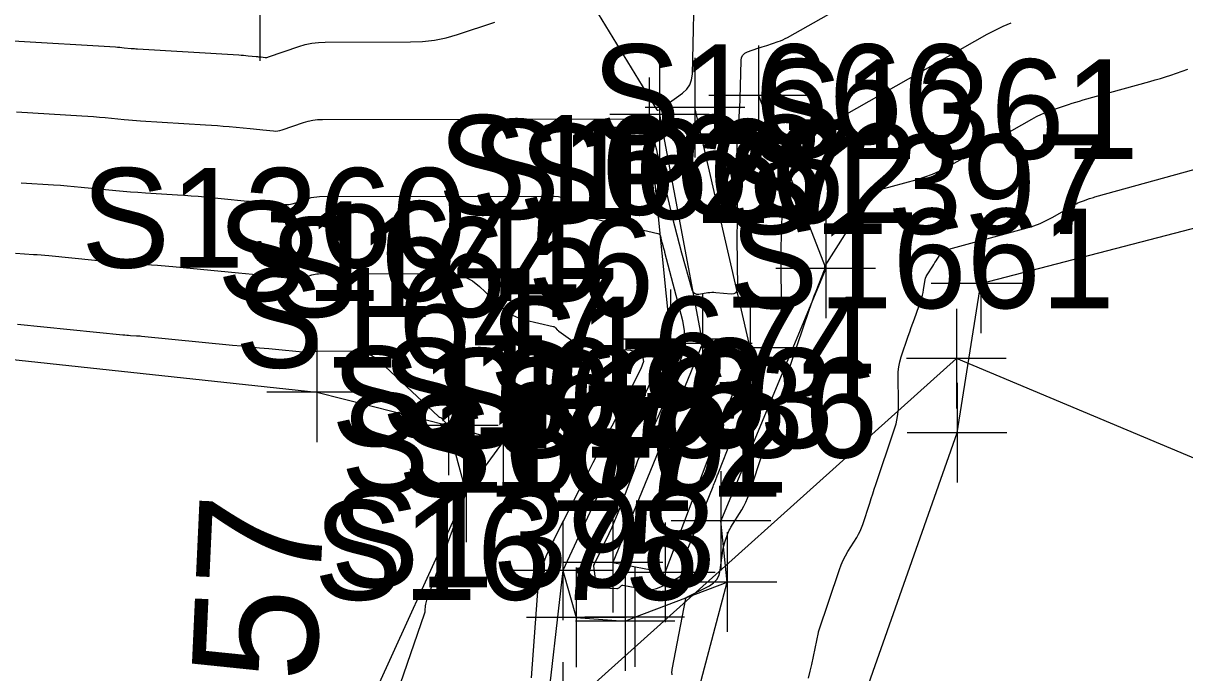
# Model space of a CAD drawing. Extents: x 816928 to 825690, y 436959 to 448212.
# Drawn here: x 818746.06 to 818792.71, y 445167.49 to 445193.57 of the extents above; entities that cross this region are included whole.
import ezdxf

# ---------------------------------------------------------------- set-up
doc = ezdxf.new("R2010")
doc.units = 0
for name, color, linetype in [('SURVEY - CONTOURS - Index with Text', 7, 'Continuous'), ('SURVEY - CONTOURS - Intermediate with optional Text', 7, 'Continuous'), ('SURVEY - DRAINAGE - Bridge Hydraulic Data - Points - Locators', 7, 'Continuous'), ('SURVEY - DRAINAGE - Bridge Hydraulic Data - Points - Numbers', 7, 'Continuous'), ('SURVEY - DRAINAGE - Bridge Hydraulic Data with Text', 7, 'Continuous'), ('SURVEY - DTM - Breaklines', 7, 'Continuous'), ('SURVEY - DTM - Breaklines - Points - Locators', 7, 'Continuous'), ('SURVEY - DTM - Breaklines - Points - Numbers', 7, 'Continuous'), ('SURVEY - NON-TRANSPORTATION - Features', 7, 'Continuous'), ('SURVEY - NON-TRANSPORTATION - Features - Points - Locators', 7, 'Continuous'), ('SURVEY - NON-TRANSPORTATION - Features - Points - Numbers', 7, 'Continuous')]:
    doc.layers.add(name, color=color, linetype=linetype)

msp = doc.modelspace()

# ---------------------------------------------------------------- linework, layer by layer
at = {"layer": 'SURVEY - CONTOURS - Index with Text'}
for points in [[(818769.01, 445194.188), (818771.507, 445190.098), (818771.515, 445190.087), (818771.525, 445190.081), (818771.537, 445190.079), (818771.55, 445190.081), (818771.595, 445190.094), (818771.605, 445190.097), (818771.614, 445190.101), (818771.623, 445190.106), (818771.631, 445190.111), (818772.535, 445190.768), (818772.705, 445190.921), (818772.828, 445191.099), (818772.904, 445191.301), (818772.933, 445191.528), (818773.026, 445195.763)], [(818745.655, 445192.864), (818749.766, 445192.618), (818749.854, 445192.612), (818749.942, 445192.606), (818750.03, 445192.598), (818750.118, 445192.59), (818750.405, 445192.562), (818750.466, 445192.556), (818750.528, 445192.551), (818750.589, 445192.546), (818750.651, 445192.542), (818754.726, 445192.298), (818754.817, 445192.292), (818754.909, 445192.285), (818755, 445192.277), (818755.091, 445192.269), (818755.419, 445192.236), (818755.468, 445192.231), (818755.518, 445192.227), (818755.567, 445192.222), (818755.617, 445192.217), (818755.778, 445192.201), (818755.812, 445192.199), (818755.846, 445192.201), (818755.88, 445192.207), (818755.913, 445192.217), (818757.125, 445192.634), (818757.386, 445192.712), (818757.652, 445192.768), (818757.921, 445192.802), (818758.194, 445192.814), (818761.616, 445192.82), (818762.097, 445192.839), (818762.572, 445192.897), (818763.041, 445192.992), (818763.504, 445193.125), (818765.005, 445193.621)]]:
    msp.add_lwpolyline(points, dxfattribs=at)
at = {"layer": 'SURVEY - CONTOURS - Intermediate with optional Text'}
for points in [[(818745.789, 445190.014), (818748.419, 445189.857), (818748.654, 445189.842), (818748.888, 445189.824), (818749.123, 445189.805), (818749.357, 445189.783), (818750.122, 445189.707), (818750.286, 445189.692), (818750.45, 445189.678), (818750.615, 445189.666), (818750.779, 445189.655), (818753.386, 445189.498), (818753.623, 445189.483), (818753.86, 445189.465), (818754.096, 445189.445), (818754.333, 445189.423), (818755.181, 445189.339), (818755.309, 445189.327), (818755.436, 445189.314), (818755.564, 445189.302), (818755.692, 445189.289), (818756.11, 445189.248), (818756.199, 445189.244), (818756.287, 445189.249), (818756.374, 445189.264), (818756.46, 445189.289), (818757.321, 445189.585), (818757.507, 445189.641), (818757.695, 445189.681), (818757.887, 445189.705), (818758.081, 445189.713), (818770.244, 445189.734), (818770.292, 445189.736), (818770.34, 445189.742), (818770.387, 445189.751), (818770.433, 445189.765), (818770.584, 445189.814), (818770.616, 445189.825), (818770.648, 445189.836), (818770.68, 445189.846), (818770.713, 445189.857), (818770.876, 445189.911), (818770.909, 445189.917), (818770.938, 445189.913), (818770.963, 445189.897), (818770.985, 445189.871), (818771.168, 445189.572), (818771.204, 445189.506), (818771.236, 445189.439), (818771.262, 445189.369), (818771.283, 445189.298), (818771.453, 445188.633), (818771.489, 445188.49), (818771.524, 445188.347), (818771.559, 445188.205), (818771.593, 445188.062), (818772.128, 445185.802), (818772.216, 445185.438), (818772.308, 445185.074), (818772.403, 445184.712), (818772.503, 445184.35), (818772.914, 445182.881), (818772.954, 445182.788), (818773.014, 445182.727), (818773.095, 445182.698), (818773.196, 445182.699), (818773.558, 445182.755), (818773.635, 445182.764), (818773.713, 445182.769), (818773.791, 445182.769), (818773.869, 445182.765), (818774.492, 445182.709), (818774.609, 445182.715), (818774.692, 445182.758), (818774.741, 445182.838), (818774.756, 445182.953), (818774.732, 445184.94), (818774.731, 445185.004), (818774.732, 445185.067), (818774.733, 445185.131), (818774.734, 445185.195), (818774.741, 445185.404), (818774.743, 445185.449), (818774.744, 445185.493), (818774.744, 445185.538), (818774.744, 445185.583), (818774.731, 445188.021), (818774.732, 445188.305), (818774.738, 445188.589), (818774.749, 445188.873), (818774.766, 445189.156), (818774.852, 445190.464), (818774.852, 445190.472), (818774.853, 445190.48), (818774.853, 445190.488), (818774.853, 445190.495), (818774.853, 445190.521), (818774.853, 445190.526), (818774.853, 445190.532), (818774.853, 445190.537), (818774.854, 445190.543), (818774.887, 445192.073), (818774.906, 445192.196), (818774.955, 445192.295), (818775.036, 445192.372), (818775.148, 445192.426), (818775.564, 445192.565), (818775.653, 445192.595), (818775.742, 445192.625), (818775.831, 445192.654), (818775.92, 445192.684), (818776.375, 445192.836), (818776.471, 445192.871), (818776.566, 445192.91), (818776.658, 445192.954), (818776.749, 445193.002), (818782.986, 445196.533)], [(818745.985, 445187.161), (818747.28, 445187.084), (818747.558, 445187.066), (818747.835, 445187.045), (818748.112, 445187.022), (818748.389, 445186.996), (818749.778, 445186.858), (818750.075, 445186.83), (818750.373, 445186.805), (818750.672, 445186.783), (818750.97, 445186.764), (818752.259, 445186.686), (818752.535, 445186.668), (818752.811, 445186.648), (818753.086, 445186.625), (818753.362, 445186.599), (818754.942, 445186.443), (818755.149, 445186.422), (818755.355, 445186.402), (818755.562, 445186.381), (818755.768, 445186.361), (818756.443, 445186.295), (818756.586, 445186.288), (818756.728, 445186.297), (818756.868, 445186.321), (818757.006, 445186.361), (818757.517, 445186.536), (818757.627, 445186.569), (818757.739, 445186.593), (818757.853, 445186.607), (818757.967, 445186.612), (818767.379, 445186.629), (818767.552, 445186.614), (818767.713, 445186.568), (818767.861, 445186.491), (818767.998, 445186.384), (818768.423, 445185.984), (818768.518, 445185.906), (818768.621, 445185.841), (818768.731, 445185.792), (818768.849, 445185.756), (818771.54, 445185.127), (818771.581, 445185.112), (818771.613, 445185.089), (818771.636, 445185.057), (818771.651, 445185.017), (818771.685, 445184.871), (818771.693, 445184.84), (818771.7, 445184.809), (818771.709, 445184.778), (818771.717, 445184.747), (818771.773, 445184.546), (818771.785, 445184.502), (818771.797, 445184.459), (818771.809, 445184.416), (818771.82, 445184.373), (818772.531, 445181.64), (818772.607, 445181.217), (818772.617, 445180.798), (818772.56, 445180.383), (818772.435, 445179.972), (818771.918, 445178.635), (818771.805, 445178.349), (818771.686, 445178.066), (818771.562, 445177.786), (818771.433, 445177.507), (818770.998, 445176.592), (818770.906, 445176.395), (818770.819, 445176.197), (818770.736, 445175.996), (818770.657, 445175.794), (818770.02, 445174.114), (818769.916, 445173.85), (818769.807, 445173.588), (818769.693, 445173.328), (818769.573, 445173.071), (818769.013, 445171.901), (818769.007, 445171.889), (818769.001, 445171.876), (818768.995, 445171.863), (818768.989, 445171.851), (818768.969, 445171.809), (818768.965, 445171.8), (818768.963, 445171.791), (818768.962, 445171.782), (818768.963, 445171.772), (818769.039, 445171.17), (818769.069, 445171.057), (818769.128, 445170.974), (818769.215, 445170.922), (818769.331, 445170.902), (818769.901, 445170.88), (818769.93, 445170.881), (818769.957, 445170.888), (818769.981, 445170.9), (818770.004, 445170.917), (818770.075, 445170.983), (818770.091, 445170.994), (818770.108, 445171.002), (818770.126, 445171.004), (818770.146, 445171.003), (818770.981, 445170.845), (818771.158, 445170.826), (818771.331, 445170.836), (818771.499, 445170.876), (818771.663, 445170.944), (818772.326, 445171.285), (818772.433, 445171.355), (818772.514, 445171.443), (818772.569, 445171.549), (818772.599, 445171.673), (818772.655, 445172.107), (818772.67, 445172.199), (818772.691, 445172.289), (818772.717, 445172.379), (818772.749, 445172.466), (818773.762, 445174.972), (818773.785, 445175.03), (818773.809, 445175.089), (818773.832, 445175.147), (818773.856, 445175.206), (818773.932, 445175.397), (818773.948, 445175.438), (818773.964, 445175.479), (818773.98, 445175.52), (818773.997, 445175.561), (818774.495, 445176.815), (818774.602, 445177.084), (818774.709, 445177.353), (818774.817, 445177.621), (818774.925, 445177.89), (818775.505, 445179.328), (818775.624, 445179.622), (818775.741, 445179.915), (818775.859, 445180.208), (818775.976, 445180.502), (818776.357, 445181.462), (818776.428, 445181.669), (818776.478, 445181.881), (818776.507, 445182.096), (818776.515, 445182.316), (818776.496, 445183.878), (818776.494, 445184.14), (818776.496, 445184.403), (818776.5, 445184.665), (818776.507, 445184.927), (818776.539, 445185.892), (818776.543, 445186.022), (818776.546, 445186.151), (818776.547, 445186.281), (818776.547, 445186.411), (818776.544, 445186.835), (818776.545, 445186.926), (818776.547, 445187.017), (818776.55, 445187.108), (818776.555, 445187.199), (818776.595, 445187.793), (818776.611, 445187.919), (818776.642, 445188.039), (818776.688, 445188.154), (818776.749, 445188.264), (818777.186, 445188.95), (818777.272, 445189.062), (818777.373, 445189.152), (818777.489, 445189.222), (818777.621, 445189.271), (818778.077, 445189.395), (818778.173, 445189.425), (818778.267, 445189.46), (818778.359, 445189.501), (818778.448, 445189.548), (818784.772, 445193.128), (818785.088, 445193.297), (818785.411, 445193.451), (818785.741, 445193.59)], [(818772.119, 445167.403), (818772.115, 445167.522), (818772.115, 445167.548), (818772.116, 445167.573), (818772.119, 445167.599), (818772.123, 445167.624), (818772.673, 445170.47), (818772.673, 445170.474), (818772.674, 445170.478), (818772.675, 445170.482), (818772.676, 445170.486), (818772.678, 445170.499), (818772.679, 445170.502), (818772.68, 445170.504), (818772.682, 445170.506), (818772.684, 445170.508), (818773.618, 445170.987), (818773.788, 445171.099), (818773.917, 445171.239), (818774.005, 445171.408), (818774.053, 445171.606), (818774.155, 445172.397), (818774.171, 445172.495), (818774.191, 445172.591), (818774.217, 445172.687), (818774.249, 445172.781), (818774.359, 445173.085), (818774.385, 445173.15), (818774.413, 445173.213), (818774.445, 445173.274), (818774.48, 445173.334), (818774.914, 445174.031), (818775.002, 445174.183), (818775.08, 445174.339), (818775.149, 445174.499), (818775.209, 445174.664), (818776.567, 445178.81), (818776.575, 445178.836), (818776.584, 445178.862), (818776.592, 445178.887), (818776.601, 445178.913), (818776.631, 445179.002), (818776.636, 445179.018), (818776.639, 445179.034), (818776.641, 445179.051), (818776.641, 445179.067), (818776.64, 445179.122), (818776.64, 445179.134), (818776.642, 445179.145), (818776.644, 445179.156), (818776.647, 445179.168), (818777.624, 445182.052), (818777.69, 445182.243), (818777.759, 445182.432), (818777.829, 445182.621), (818777.902, 445182.808), (818778.243, 445183.666), (818778.246, 445183.674), (818778.248, 445183.682), (818778.249, 445183.69), (818778.249, 445183.699), (818778.249, 445183.726), (818778.249, 445183.732), (818778.249, 445183.738), (818778.249, 445183.744), (818778.249, 445183.75), (818778.251, 445183.799), (818778.252, 445183.809), (818778.254, 445183.819), (818778.258, 445183.828), (818778.263, 445183.837), (818779.053, 445185.077), (818779.181, 445185.277), (818779.308, 445185.477), (818779.436, 445185.678), (818779.564, 445185.878), (818779.981, 445186.532), (818780.079, 445186.66), (818780.195, 445186.764), (818780.329, 445186.844), (818780.48, 445186.9), (818781.956, 445187.303), (818782.269, 445187.399), (818782.574, 445187.514), (818782.871, 445187.647), (818783.16, 445187.799), (818786.558, 445189.723), (818786.751, 445189.826), (818786.948, 445189.92), (818787.15, 445190.005), (818787.356, 445190.08), (818788.035, 445190.31), (818788.181, 445190.359), (818788.327, 445190.405), (818788.474, 445190.449), (818788.622, 445190.491), (818791.303, 445191.233), (818791.515, 445191.294), (818791.726, 445191.357), (818791.936, 445191.423), (818792.146, 445191.492), (818792.828, 445191.723)], [(818777.596, 445167.277), (818777.665, 445167.549), (818777.726, 445167.824), (818777.992, 445169.105), (818777.993, 445169.108), (818777.994, 445169.111), (818777.994, 445169.114), (818777.995, 445169.117), (818777.997, 445169.127), (818777.997, 445169.129), (818777.998, 445169.131), (818777.998, 445169.133), (818777.999, 445169.135), (818778.838, 445171.633), (818778.908, 445171.823), (818778.989, 445172.008), (818779.08, 445172.188), (818779.182, 445172.364), (818779.533, 445172.927), (818779.604, 445173.05), (818779.668, 445173.176), (818779.723, 445173.306), (818779.772, 445173.44), (818780.055, 445174.304), (818780.116, 445174.489), (818780.177, 445174.674), (818780.239, 445174.859), (818780.301, 445175.044), (818781.029, 445177.202), (818781.113, 445177.489), (818781.171, 445177.78), (818781.204, 445178.075), (818781.211, 445178.375), (818781.193, 445179.358), (818781.198, 445179.568), (818781.221, 445179.774), (818781.262, 445179.978), (818781.321, 445180.179), (818781.6, 445181.004), (818781.661, 445181.181), (818781.722, 445181.358), (818781.784, 445181.534), (818781.847, 445181.709), (818782.12, 445182.461), (818782.152, 445182.559), (818782.179, 445182.659), (818782.201, 445182.759), (818782.218, 445182.861), (818782.263, 445183.197), (818782.276, 445183.267), (818782.297, 445183.335), (818782.325, 445183.401), (818782.36, 445183.463), (818782.585, 445183.816), (818782.631, 445183.887), (818782.676, 445183.958), (818782.721, 445184.029), (818782.766, 445184.1), (818782.913, 445184.331), (818782.948, 445184.377), (818782.989, 445184.413), (818783.037, 445184.442), (818783.09, 445184.461), (818786.382, 445185.361), (818786.641, 445185.44), (818786.893, 445185.535), (818787.139, 445185.645), (818787.379, 445185.771), (818788.344, 445186.318), (818788.414, 445186.355), (818788.485, 445186.389), (818788.558, 445186.42), (818788.633, 445186.447), (818788.879, 445186.531), (818788.932, 445186.548), (818788.985, 445186.565), (818789.038, 445186.581), (818789.092, 445186.596), (818793.125, 445187.713)], [(818745.757, 445184.333), (818746.474, 445184.29), (818746.628, 445184.28), (818746.781, 445184.269), (818746.935, 445184.256), (818747.088, 445184.241), (818749.857, 445183.968), (818750.076, 445183.947), (818750.296, 445183.929), (818750.516, 445183.912), (818750.736, 445183.898), (818751.454, 445183.855), (818751.608, 445183.845), (818751.762, 445183.833), (818751.916, 445183.82), (818752.069, 445183.806), (818754.704, 445183.546), (818754.989, 445183.518), (818755.274, 445183.49), (818755.559, 445183.461), (818755.844, 445183.433), (818756.982, 445183.321), (818757.077, 445183.317), (818757.172, 445183.322), (818757.264, 445183.338), (818757.356, 445183.365), (818757.654, 445183.467), (818757.718, 445183.487), (818757.784, 445183.5), (818757.85, 445183.509), (818757.917, 445183.512), (818763.075, 445183.52), (818763.442, 445183.489), (818763.784, 445183.391), (818764.099, 445183.229), (818764.389, 445183.001), (818765.296, 445182.149), (818765.497, 445181.983), (818765.714, 445181.847), (818765.947, 445181.742), (818766.197, 445181.666), (818767.338, 445181.4), (818767.367, 445181.39), (818767.394, 445181.377), (818767.418, 445181.359), (818767.44, 445181.338), (818767.507, 445181.26), (818767.522, 445181.244), (818767.538, 445181.229), (818767.555, 445181.214), (818767.572, 445181.201), (818768.139, 445180.807), (818768.263, 445180.731), (818768.394, 445180.673), (818768.532, 445180.632), (818768.676, 445180.609), (818770.451, 445180.441), (818770.762, 445180.367), (818770.934, 445180.217), (818770.968, 445179.991), (818770.864, 445179.689), (818769.695, 445177.399), (818769.444, 445176.908), (818769.194, 445176.417), (818768.943, 445175.926), (818768.693, 445175.436), (818767.412, 445172.927), (818767.378, 445172.859), (818767.345, 445172.791), (818767.312, 445172.722), (818767.281, 445172.652), (818767.159, 445172.381), (818767.147, 445172.354), (818767.135, 445172.327), (818767.122, 445172.301), (818767.109, 445172.275), (818767.065, 445172.19), (818767.056, 445172.171), (818767.048, 445172.153), (818767.04, 445172.134), (818767.033, 445172.115), (818766.84, 445171.591), (818766.803, 445171.478), (818766.774, 445171.363), (818766.753, 445171.246), (818766.741, 445171.128), (818766.465, 445167.289)], [(818745.83, 445181.483), (818750.07, 445181.064), (818750.144, 445181.057), (818750.219, 445181.051), (818750.293, 445181.045), (818750.367, 445181.04), (818750.609, 445181.026), (818750.661, 445181.022), (818750.713, 445181.019), (818750.765, 445181.014), (818750.817, 445181.009), (818754.466, 445180.649), (818754.829, 445180.613), (818755.193, 445180.577), (818755.556, 445180.541), (818755.92, 445180.505), (818757.549, 445180.345), (818757.583, 445180.343), (818757.615, 445180.345), (818757.648, 445180.351), (818757.68, 445180.36), (818757.783, 445180.395), (818757.806, 445180.402), (818757.828, 445180.407), (818757.851, 445180.41), (818757.875, 445180.411), (818759.316, 445180.413), (818759.614, 445180.387), (818759.892, 445180.308), (818760.148, 445180.176), (818760.384, 445179.991), (818762.739, 445177.779), (818762.748, 445177.771), (818762.759, 445177.764), (818762.77, 445177.759), (818762.782, 445177.755), (818762.823, 445177.746), (818762.831, 445177.743), (818762.839, 445177.739), (818762.846, 445177.734), (818762.852, 445177.728), (818763.031, 445177.52), (818763.067, 445177.474), (818763.097, 445177.425), (818763.121, 445177.373), (818763.14, 445177.318), (818763.843, 445174.755), (818763.844, 445174.753), (818763.844, 445174.752), (818763.845, 445174.75), (818763.845, 445174.748), (818763.847, 445174.742), (818763.847, 445174.741), (818763.847, 445174.74), (818763.847, 445174.738), (818763.847, 445174.737), (818763.846, 445174.729), (818763.845, 445174.728), (818763.845, 445174.726), (818763.844, 445174.724), (818763.844, 445174.723), (818762.258, 445170.402), (818762.24, 445170.349), (818762.226, 445170.294), (818762.216, 445170.239), (818762.21, 445170.182), (818762.197, 445169.997), (818762.193, 445169.958), (818762.186, 445169.919), (818762.177, 445169.881), (818762.165, 445169.843), (818760.787, 445165.836)]]:
    msp.add_lwpolyline(points, dxfattribs=at)
at = {"layer": 'SURVEY - DRAINAGE - Bridge Hydraulic Data - Points - Locators'}
for p, q in [((818755.569, 445196.059), (818755.569, 445192.059)), ((818784.519, 445185.127), (818784.519, 445181.127)), ((818786.519, 445183.127), (818782.519, 445183.127)), ((818757.852, 445180.757), (818757.852, 445176.757)), ((818763.137, 445179.424), (818763.137, 445175.424)), ((818783.56, 445179.129), (818783.56, 445175.129)), ((818759.852, 445178.757), (818755.852, 445178.757)), ((818765.335, 445178.778), (818765.335, 445174.778)), ((818765.137, 445177.424), (818761.137, 445177.424)), ((818767.335, 445176.778), (818763.335, 445176.778)), ((818763.85, 445176.738), (818763.85, 445172.738)), ((818785.56, 445177.129), (818781.56, 445177.129)), ((818765.85, 445174.738), (818761.85, 445174.738))]:
    msp.add_line(p, q, dxfattribs=at)
at = {"layer": 'SURVEY - DRAINAGE - Bridge Hydraulic Data with Text'}
msp.add_line((818710.411, 445183.877), (818757.852, 445178.757), dxfattribs=at)
for points in [[(818784.519, 445183.127), (818807.177, 445189.01), (818822.594, 445179.409), (818846.448, 445165.831), (818864.623, 445142.909), (818851.635, 445125.23), (818852.677, 445121.979), (818854.948, 445121.819)], [(818757.852, 445178.757), (818763.137, 445177.424), (818765.335, 445176.778), (818763.85, 445174.738), (818755.626, 445156.7), (818750.208, 445134.422), (818726.213, 445122.086), (818716.658, 445105.767), (818715.142, 445099.822), (818717.206, 445098.8), (818722.312, 445098.543), (818727.161, 445104.474), (818730.225, 445110.91), (818749.677, 445108.675), (818763.087, 445111.464), (818772.094, 445127.037), (818775.326, 445153.725), (818783.56, 445177.129), (818784.519, 445183.127)]]:
    msp.add_lwpolyline(points, dxfattribs=at)
at = {"layer": 'SURVEY - DTM - Breaklines'}
for points in [[(818775.594, 445190.672), (818778.289, 445183.723), (818774.081, 445173.592)], [(818771.613, 445189.909), (818773.341, 445180.715), (818769.744, 445171.916), (818771.846, 445171.52), (818775.25, 445180.544), (818773.039, 445190.187)], [(818771.204, 445189.391), (818772.049, 445180.881), (818767.735, 445171.597), (818768.27, 445169.716), (818770.235, 445169.563), (818770.62, 445169.723), (818774.327, 445171.13)], [(818767.735, 445171.597), (818767.024, 445165.419), (818760.128, 445148.609), (818758.654, 445134.039), (818739.695, 445122.788), (818725.393, 445116.954), (818717.484, 445105.034), (818719.452, 445102.001), (818727.622, 445113.557), (818737.539, 445117.921), (818760.429, 445117.38), (818769.199, 445151.75), (818774.327, 445171.13), (818774.081, 445173.592)]]:
    msp.add_lwpolyline(points, dxfattribs=at)
at = {"layer": 'SURVEY - DTM - Breaklines - Points - Locators'}
for p, q in [((818775.594, 445192.672), (818775.594, 445188.672)), ((818773.039, 445192.187), (818773.039, 445188.187)), ((818771.613, 445191.909), (818771.613, 445187.909)), ((818771.204, 445191.391), (818771.204, 445187.391)), ((818777.594, 445190.672), (818773.594, 445190.672)), ((818773.613, 445189.909), (818769.613, 445189.909)), ((818775.039, 445190.187), (818771.039, 445190.187)), ((818773.204, 445189.391), (818769.204, 445189.391)), ((818778.289, 445185.723), (818778.289, 445181.723)), ((818780.289, 445183.723), (818776.289, 445183.723)), ((818772.049, 445182.881), (818772.049, 445178.881)), ((818773.341, 445182.715), (818773.341, 445178.715)), ((818775.25, 445182.544), (818775.25, 445178.544)), ((818774.049, 445180.881), (818770.049, 445180.881)), ((818775.341, 445180.715), (818771.341, 445180.715)), ((818777.25, 445180.544), (818773.25, 445180.544)), ((818774.081, 445175.592), (818774.081, 445171.592)), ((818769.744, 445173.916), (818769.744, 445169.916)), ((818767.735, 445173.597), (818767.735, 445169.597)), ((818771.846, 445173.52), (818771.846, 445169.52)), ((818776.081, 445173.592), (818772.081, 445173.592)), ((818774.327, 445173.13), (818774.327, 445169.13)), ((818769.735, 445171.597), (818765.735, 445171.597)), ((818771.744, 445171.916), (818767.744, 445171.916)), ((818768.27, 445171.716), (818768.27, 445167.716)), ((818770.235, 445171.563), (818770.235, 445167.563)), ((818770.62, 445171.723), (818770.62, 445167.723)), ((818773.846, 445171.52), (818769.846, 445171.52)), ((818776.327, 445171.13), (818772.327, 445171.13)), ((818770.27, 445169.716), (818766.27, 445169.716)), ((818772.62, 445169.723), (818768.62, 445169.723)), ((818772.235, 445169.563), (818768.235, 445169.563))]:
    msp.add_line(p, q, dxfattribs=at)
at = {"layer": 'SURVEY - NON-TRANSPORTATION - Features'}
msp.add_lwpolyline([(818878.723, 445102.028), (818832.174, 445159.68), (818783.535, 445180.107), (818767.737, 445165.919), (818720.129, 445113.759)], dxfattribs=at)
at = {"layer": 'SURVEY - NON-TRANSPORTATION - Features - Points - Locators'}
for p, q in [((818783.535, 445182.107), (818783.535, 445178.107)), ((818785.535, 445180.107), (818781.535, 445180.107)), ((818767.737, 445167.919), (818767.737, 445163.919))]:
    msp.add_line(p, q, dxfattribs=at)

# ---------------------------------------------------------------- texts
at = {"layer": 'SURVEY - DRAINAGE - Bridge Hydraulic Data - Points - Numbers'}
for s, p in [('S1361', (818775.389, 445188.127)), ('S1360', (818748.391, 445183.757)), ('S1645', (818753.849, 445182.424)), ('S1661', (818774.429, 445182.129)), ('S1646', (818755.937, 445181.778)), ('S1647', (818754.562, 445179.738))]:
    msp.add_text(s, height=4, dxfattribs=at).set_placement(p)
at = {"layer": 'SURVEY - DRAINAGE - Bridge Hydraulic Data with Text'}
msp.add_text('POT 30+46.57', height=5, rotation=87.3672, dxfattribs=at).set_placement((818756.144, 445130.876))
at = {"layer": 'SURVEY - DTM - Breaklines - Points - Numbers'}
for s, p in [('S1666', (818768.891, 445188.723)), ('S1668', (818762.714, 445185.881)), ('S1667', (818764.053, 445185.715)), ('SP262', (818765.962, 445185.544)), ('S1674', (818764.793, 445178.592)), ('S1673', (818760.456, 445176.916)), ('S1669', (818758.431, 445176.597)), ('SP263', (818762.558, 445176.52)), ('S1686', (818764.929, 445176.13)), ('S1670', (818758.809, 445174.716)), ('S1671', (818761.104, 445174.563)), ('S1672', (818761.332, 445174.723)), ('S1675', (818757.736, 445170.419))]:
    msp.add_text(s, height=4, dxfattribs=at).set_placement(p)
at = {"layer": 'SURVEY - NON-TRANSPORTATION - Features - Points - Numbers'}
for s, p in [('S1397', (818774.247, 445185.107)), ('S1398', (818758.402, 445170.919))]:
    msp.add_text(s, height=4, dxfattribs=at).set_placement(p)

doc.saveas('drawing.dxf')
